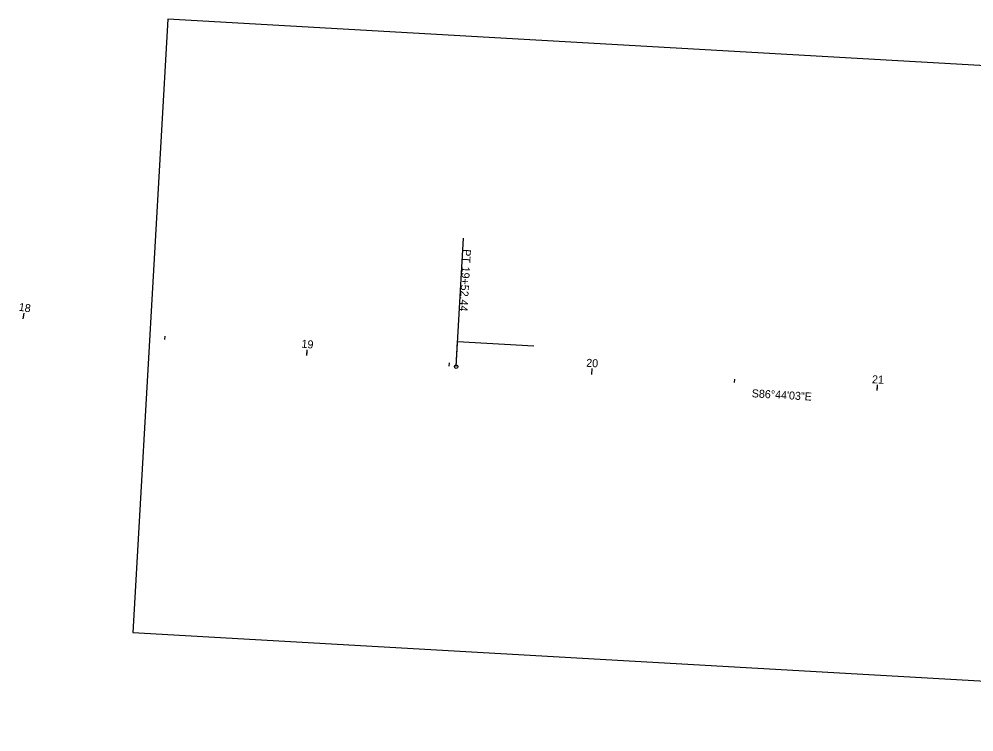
# Model space of a CAD drawing. Extents: x 2273904 to 2275374, y 654586 to 654897.
# Drawn here: x 2274305.2 to 2274639.3, y 654585.8 to 654835.2 of the extents above; entities that cross this region are included whole.
import ezdxf

# ---------------------------------------------------------------- set-up
doc = ezdxf.new("R2010")
doc.units = 0
for name, color, linetype in [('DR_P_Ditch', 7, 'Continuous'), ('DR_P_Erosion_Control', 7, 'Continuous'), ('GK_Drainage_Nodes', 7, 'Continuous'), ('SC_Scratch1', 7, 'Continuous'), ('SC_Scratch10', 7, 'Continuous'), ('SH_Named_Boundary', 7, 'Continuous')]:
    doc.layers.add(name, color=color, linetype=linetype)

msp = doc.modelspace()

# ---------------------------------------------------------------- linework, layer by layer
at = {"layer": 'DR_P_Ditch'}
for p, q in [((2274458.12, 654713.61), (2274460.68, 654758.54)), ((2274306.67, 654730.36), (2274306.87, 654731.55)), ((2274405.83, 654717.55), (2274405.94, 654718.75)), ((2274505.6, 654710.9), (2274505.72, 654712.9)), ((2274605.44, 654705.2), (2274605.51, 654706.4))]:
    msp.add_line(p, q, dxfattribs=at)
msp.add_circle((2274458.12, 654713.61), 0.6, dxfattribs=at)
at = {"layer": 'DR_P_Erosion_Control'}
for p, q in [((2274458.12, 654713.61), (2274460.68, 654758.54)), ((2274306.67, 654730.36), (2274307, 654732.34)), ((2274356.14, 654723.09), (2274356.29, 654724.28)), ((2274458.12, 654713.61), (2274458.62, 654722.41)), ((2274458.62, 654722.41), (2274485.34, 654720.89)), ((2274405.83, 654717.55), (2274406.02, 654719.54)), ((2274455.68, 654713.75), (2274455.75, 654714.95)), ((2274505.6, 654710.9), (2274505.72, 654712.9)), ((2274555.52, 654708.05), (2274555.59, 654709.25)), ((2274605.44, 654705.2), (2274605.55, 654707.2))]:
    msp.add_line(p, q, dxfattribs=at)
msp.add_circle((2274458.12, 654713.61), 0.6, dxfattribs=at)
msp.add_circle((2274458.12, 654713.61), 0.6, dxfattribs=at)
at = {"layer": 'SC_Scratch1'}
for p, q in [((2274458.12, 654713.61), (2274460.68, 654758.54)), ((2274505.6, 654710.9), (2274505.72, 654712.9))]:
    msp.add_line(p, q, dxfattribs=at)
msp.add_circle((2274458.12, 654713.61), 0.6, dxfattribs=at)
at = {"layer": 'SH_Named_Boundary'}
msp.add_lwpolyline([(2274345.01, 654620.55), (2274954.02, 654585.8), (2274966.26, 654800.45), (2274357.26, 654835.2)], close=True, dxfattribs=at)

# ---------------------------------------------------------------- texts
at = {"layer": 'DR_P_Ditch'}
for s, rotation, p in [('PT', 266.7343, (2274460.51, 654754.77)), ('19+52.44', 266.7343, (2274460.17, 654748.69)), ('20', 356.7343, (2274503.56, 654713.57))]:
    msp.add_text(s, height=2.8, rotation=rotation, dxfattribs=at).set_placement(p)
at = {"layer": 'DR_P_Erosion_Control'}
for s, rotation, p in [('PT', 266.7343, (2274460.51, 654754.77)), ('19+52.44', 266.7343, (2274460.17, 654748.69)), ('18', 350.638, (2274304.93, 654733.23)), ('19', 354.6371, (2274403.91, 654720.29)), ('20', 356.7343, (2274503.56, 654713.57)), ('21', 356.7343, (2274603.56, 654707.81))]:
    msp.add_text(s, height=2.8, rotation=rotation, dxfattribs=at).set_placement(p)
at = {"layer": 'GK_Drainage_Nodes'}
msp.add_text('S86°44\'03"E', height=2.8, rotation=356.7343, dxfattribs=at).set_placement((2274561.48, 654702.9))
msp.add_text('S86°44\'03"E', height=2.8, rotation=356.7343, dxfattribs=at).set_placement((2274561.48, 654702.9))
at = {"layer": 'SC_Scratch1'}
for s, rotation, p in [('PT', 266.7343, (2274460.51, 654754.77)), ('19+52.44', 266.7343, (2274460.17, 654748.69)), ('20', 356.7343, (2274503.56, 654713.57))]:
    msp.add_text(s, height=2.8, rotation=rotation, dxfattribs=at).set_placement(p)
at = {"layer": 'SC_Scratch10'}
msp.add_text('S86°44\'03"E', height=2.8, rotation=356.7343, dxfattribs=at).set_placement((2274561.48, 654702.9))

doc.saveas('drawing.dxf')
